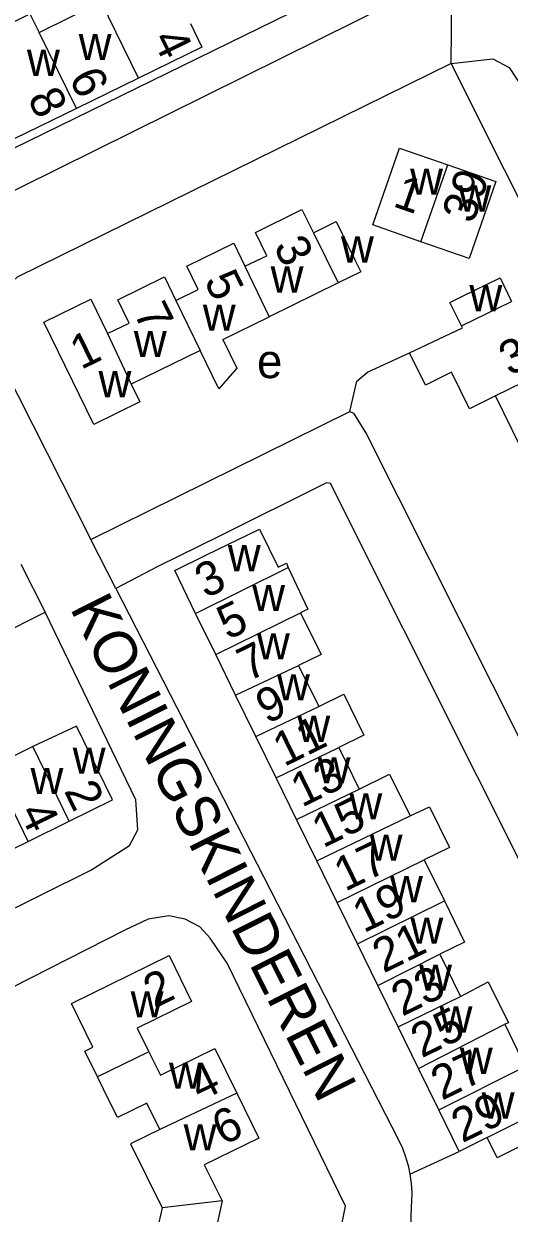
# Model space of a CAD drawing. Extents: x 159441 to 162086, y 388175 to 389787.
# Drawn here: x 161637.2 to 161694.2, y 388554.8 to 388694.6 of the extents above; entities that cross this region are included whole.
import ezdxf

# ---------------------------------------------------------------- set-up
doc = ezdxf.new("R2010")
doc.units = 0
for name, color, linetype in [('BLT_Basislijn', 7, 'Continuous'), ('BLT_Bebouwing', 7, 'Continuous'), ('BLT_Centroide', 7, 'Continuous'), ('BLT_Huisnummer', 7, 'Continuous'), ('BLT_Huisnummer_ tussenligend', 7, 'Continuous'), ('BLT_Onderverdeling_panden', 7, 'Continuous'), ('BLT_Straatnaam', 7, 'Continuous'), ('BLT_Vlakafsluiter', 7, 'Continuous')]:
    doc.layers.add(name, color=color, linetype=linetype)

msp = doc.modelspace()

# ---------------------------------------------------------------- linework, layer by layer
at = {"layer": 'BLT_Basislijn'}
for p, q in [((161647.97, 388628.23), (161645.03, 388633.99)), ((161636.83, 388631.07), (161639.68, 388625.42)), ((161596.89, 388604.02), (161639.68, 388625.42))]:
    msp.add_line(p, q, dxfattribs=at)
for points in [[(161578.12, 388651.71), (161684.78, 388703.89)], [(161685.4, 388696.77), (161683.76, 388696.15), (161680.57, 388697.06), (161588.6, 388651.51)], [(161687.38, 388689.93), (161692.29, 388690.47), (161694.21, 388689.46), (161697.24, 388684.8), (161705.87, 388667.98)], [(161687.38, 388689.93), (161636.39, 388664.83), (161633.72, 388662.46), (161632.99, 388658.94), (161633.07, 388657.62), (161645.03, 388633.99)], [(161699.94, 388664.93), (161687.38, 388689.93)], [(161675.47, 388649.04), (161676.32, 388652.58), (161677.56, 388653.64), (161682.48, 388655.92)], [(161645.03, 388633.99), (161675.47, 388649.04)], [(161675.47, 388649.04), (161675.89, 388648.83), (161677.43, 388646.38), (161718.1, 388565.45)], [(161700.24, 388567.96), (161707.73, 388571.69), (161673.2, 388640.55), (161672.73, 388640.65), (161660.17, 388634.37), (161652.91, 388630.82), (161647.97, 388628.23)], [(161647.97, 388628.23), (161681.21, 388563.42), (161681.65, 388562.44), (161682.03, 388561.43), (161682.33, 388560.4), (161682.54, 388559.38)], [(161609.65, 388577.57), (161645.06, 388595.11), (161649.6, 388598.01), (161650.55, 388599.86), (161650.33, 388603.36), (161639.68, 388625.42)], [(161663.91, 388500), (161674.95, 388555.6), (161661.05, 388584.17), (161659.08, 388587.13), (161657.86, 388588.44), (161656.13, 388589.35), (161654.21, 388589.74), (161651.76, 388589.36), (161649.03, 388588.05), (161604.73, 388565.54), (161604.29, 388565.36), (161603.88, 388565.12), (161603.52, 388564.82), (161603.22, 388564.45), (161602.98, 388564.04), (161602.82, 388563.6), (161602.73, 388563.14), (161602.72, 388562.66), (161602.8, 388562.2), (161602.94, 388561.75), (161603.06, 388561.5), (161605.95, 388555.2), (161608.55, 388550.23)], [(161682.54, 388559.38), (161688.31, 388562.06)], [(161682.54, 388559.38), (161682.69, 388558.28), (161682.76, 388557.21), (161682.74, 388556.13), (161682.7, 388555.61), (161682.37, 388545.64), (161682.35, 388544.95), (161682.4, 388544.26), (161682.54, 388543.58), (161682.76, 388542.92), (161683.04, 388542.29), (161683.4, 388541.7), (161683.83, 388541.16), (161684.31, 388540.67), (161684.85, 388540.23), (161685.44, 388539.86), (161686.06, 388539.57), (161686.71, 388539.34), (161687.39, 388539.19), (161687.69, 388539.15), (161721.9, 388532.46), (161722.81, 388532.27)]]:
    msp.add_lwpolyline(points, dxfattribs=at)
at = {"layer": 'BLT_Bebouwing'}
for p, q in [((161638.97, 388693.57), (161646.27, 388697.19)), ((161660.54, 388657.5), (161665.98, 388660.17)), ((161638.23, 388609.64), (161633.41, 388607.27)), ((161638.82, 388609.93), (161638.23, 388609.64)), ((161637.69, 388598.5), (161642.51, 388600.88)), ((161632.84, 388596.11), (161637.69, 388598.5))]:
    msp.add_line(p, q, dxfattribs=at)
for points in [[(161631.69, 388689.99), (161633.71, 388690.98), (161632.62, 388693.2), (161637.88, 388695.79), (161638.97, 388693.57)], [(161656.75, 388694.62), (161658.1, 388691.85), (161650.66, 388688.22)], [(161650.66, 388688.22), (161643.35, 388684.65)], [(161643.35, 388684.65), (161636.03, 388681.07)], [(161683.83, 388668.99), (161678.17, 388670.96), (161681.31, 388680), (161686.98, 388678.04)], [(161686.98, 388678.04), (161692.64, 388676.07), (161689.49, 388667.02), (161683.83, 388668.99)], [(161665.71, 388667.34), (161664.39, 388670.06), (161669.85, 388672.76), (161671.19, 388670.03)], [(161671.19, 388670.03), (161673.88, 388671.35), (161676.08, 388666.86), (161676.77, 388665.45), (161674.09, 388664.14)], [(161657.66, 388663.38), (161656.32, 388666.12), (161661.83, 388668.82), (161663.15, 388666.1)], [(161663.15, 388666.1), (161665.71, 388667.34)], [(161649.55, 388659.42), (161648.23, 388662.15), (161653.69, 388664.84), (161655.03, 388662.09)], [(161674.09, 388664.14), (161665.98, 388660.17)], [(161688.59, 388659.09), (161687.24, 388661.85), (161688.65, 388662.54), (161693.14, 388664.74), (161694.49, 388661.96)], [(161655.03, 388662.09), (161657.66, 388663.38)], [(161649.79, 388652.24), (161650.81, 388650.15), (161645.4, 388647.5), (161639.51, 388659.53), (161645.03, 388662.23), (161646.99, 388658.18)], [(161646.99, 388658.18), (161649.55, 388659.42)], [(161682.48, 388655.92), (161688.71, 388658.85), (161688.59, 388659.09)], [(161660.54, 388657.5), (161662.19, 388654.13), (161660.1, 388651.69), (161657.89, 388656.21)], [(161657.89, 388656.21), (161649.79, 388652.24)], [(161692.6, 388650.88), (161689.53, 388649.33), (161687.42, 388653.66), (161684.36, 388652.13), (161682.48, 388655.92)], [(161696.56, 388642.79), (161692.6, 388650.88)], [(161657.36, 388625.3), (161654.9, 388630.33), (161658.65, 388632.17), (161664.88, 388635.21), (161667.07, 388630.72), (161668.02, 388631.19), (161668.25, 388630.7)], [(161668.25, 388630.7), (161670.53, 388625.8), (161669.69, 388625.37)], [(161659.73, 388620.45), (161657.36, 388625.3)], [(161669.69, 388625.37), (161672.09, 388620.47), (161669.45, 388619.18)], [(161662.06, 388615.7), (161659.73, 388620.45)], [(161669.45, 388619.18), (161671.82, 388614.35)], [(161664.45, 388610.82), (161662.06, 388615.7)], [(161671.82, 388614.35), (161674.78, 388615.8), (161677.13, 388610.99), (161674.17, 388609.54)], [(161642.51, 388600.88), (161647.58, 388603.38), (161643.37, 388612.02), (161638.82, 388609.93)], [(161666.83, 388605.95), (161664.45, 388610.82)], [(161674.17, 388609.54), (161676.58, 388604.62)], [(161669.22, 388601.07), (161666.83, 388605.95)], [(161676.58, 388604.62), (161680.15, 388606.38), (161682.55, 388601.49)], [(161682.55, 388601.49), (161684.85, 388602.56), (161687.18, 388597.79), (161684.21, 388596.34)], [(161671.61, 388596.2), (161669.22, 388601.07)], [(161673.99, 388591.32), (161671.61, 388596.2)], [(161684.21, 388596.34), (161686.59, 388591.49)], [(161676.38, 388586.44), (161673.99, 388591.32)], [(161686.59, 388591.49), (161688.96, 388586.65), (161686.06, 388585.23)], [(161678.77, 388581.57), (161676.38, 388586.44)], [(161642.75, 388579.44), (161654.25, 388585.1), (161656.89, 388579.69), (161650.49, 388576.55), (161651.85, 388573.77)], [(161686.06, 388585.23), (161688.48, 388580.28)], [(161681.15, 388576.69), (161678.77, 388581.57)], [(161688.48, 388580.28), (161691.74, 388582), (161694.12, 388577.15), (161693.68, 388576.99)], [(161645.28, 388574.31), (161642.75, 388579.44)], [(161683.54, 388571.81), (161681.15, 388576.69)], [(161693.68, 388576.99), (161696.1, 388572.05)], [(161645.83, 388570.81), (161644.33, 388573.85), (161645.28, 388574.31)], [(161651.85, 388573.77), (161653.22, 388571), (161659.62, 388574.14), (161662.2, 388568.88)], [(161685.92, 388566.94), (161683.54, 388571.81)], [(161653.14, 388564.64), (161651.61, 388567.74), (161648.18, 388566.04), (161646.54, 388569.36), (161645.83, 388570.81)], [(161662.2, 388568.88), (161664.78, 388563.61), (161658.37, 388560.47), (161660.46, 388556.25)], [(161688.31, 388562.06), (161685.92, 388566.94)], [(161653.14, 388564.64), (161649.7, 388562.95), (161653.41, 388555.43)], [(161695.63, 388565.67), (161696.8, 388563.28), (161692.79, 388561.31), (161691.63, 388563.68)], [(161691.63, 388563.68), (161688.31, 388562.06)], [(161660.46, 388556.25), (161659.48, 388551.74), (161666.45, 388550.26), (161665.22, 388544.53)], [(161653.41, 388555.43), (161652.85, 388552.82), (161656.62, 388552.02), (161655.46, 388546.55)]]:
    msp.add_lwpolyline(points, dxfattribs=at)
at = {"layer": 'BLT_Onderverdeling_panden'}
for p, q in [((161650.66, 388688.22), (161646.27, 388697.19)), ((161643.35, 388684.65), (161638.97, 388693.57)), ((161683.83, 388668.99), (161686.98, 388678.04)), ((161671.19, 388670.03), (161674.09, 388664.14)), ((161663.15, 388666.1), (161665.98, 388660.17)), ((161655.03, 388662.09), (161657.89, 388656.21)), ((161688.59, 388659.09), (161694.49, 388661.96)), ((161646.99, 388658.18), (161649.79, 388652.24)), ((161701.2, 388655.1), (161692.6, 388650.88)), ((161657.36, 388625.3), (161668.25, 388630.7)), ((161659.73, 388620.45), (161669.69, 388625.37)), ((161662.06, 388615.7), (161669.45, 388619.18)), ((161664.45, 388610.82), (161671.82, 388614.35)), ((161642.51, 388600.88), (161638.23, 388609.64)), ((161666.83, 388605.95), (161674.17, 388609.54)), ((161637.69, 388598.5), (161633.41, 388607.27)), ((161669.22, 388601.07), (161676.58, 388604.62)), ((161671.61, 388596.2), (161682.55, 388601.49)), ((161673.99, 388591.32), (161684.21, 388596.34)), ((161676.38, 388586.44), (161686.59, 388591.49)), ((161678.77, 388581.57), (161686.06, 388585.23)), ((161681.15, 388576.69), (161688.48, 388580.28)), ((161683.54, 388571.81), (161693.68, 388576.99)), ((161651.85, 388573.77), (161645.83, 388570.81)), ((161685.92, 388566.94), (161696.1, 388572.05)), ((161662.2, 388568.88), (161653.14, 388564.64)), ((161691.63, 388563.68), (161695.63, 388565.67)), ((161660.46, 388556.25), (161653.41, 388555.43))]:
    msp.add_line(p, q, dxfattribs=at)
at = {"layer": 'BLT_Vlakafsluiter'}
msp.add_line((161687.38, 388689.93), (161687.48, 388698.35), dxfattribs=at)

# ---------------------------------------------------------------- texts
at = {"layer": 'BLT_Centroide'}
for s, p in [('w', (161643.61, 388690.34)), ('w', (161637.53, 388688.48)), ('w', (161682.56, 388674.5)), ('w', (161688.23, 388672.53)), ('w', (161674.44, 388666.54)), ('w', (161666.17, 388663.01)), ('w', (161689.53, 388660.82)), ('w', (161658.2, 388658.53)), ('w', (161650.09, 388655.42)), ('e', (161664.57, 388652.95)), ('w', (161645.94, 388650.71)), ('w', (161661.14, 388630.25)), ('w', (161664, 388625.56)), ('w', (161664.56, 388619.88)), ('w', (161666.92, 388615.06)), ('w', (161669.31, 388610.19)), ('w', (161642.91, 388606.44)), ('w', (161671.69, 388605.31)), ('w', (161637.95, 388604.06)), ('w', (161675.43, 388601.09)), ('w', (161677.81, 388596.22)), ('w', (161680.2, 388591.34)), ('w', (161682.59, 388586.47)), ('w', (161683.62, 388580.94)), ('w', (161649.72, 388577.8)), ('w', (161686.02, 388576.03)), ('w', (161688.4, 388571.16)), ('w', (161654.23, 388569.41)), ('w', (161690.97, 388565.91)), ('w', (161655.95, 388562.16))]:
    msp.add_text(s, height=4, dxfattribs=at).set_placement(p)
at = {"layer": 'BLT_Huisnummer'}
for s, rotation, p in [('4', 296.0386, (161652.22, 388692.83)), ('6', 296.0386, (161642.41, 388688.25)), ('1', 340.8186, (161680.41, 388673.19)), ('39', 70.8239, (161689.97, 388670.98)), ('3', 296.0935, (161666.46, 388668.45)), ('7', 296.0935, (161650.02, 388660.65)), ('1', 26.0937, (161643.89, 388653.89)), ('37', 26.0328, (161694.27, 388653.14)), ('3', 26.0729, (161658.55, 388627.01)), ('7', 26.0729, (161663.53, 388617.23)), ('11', 26.0729, (161667.74, 388607.22)), ('2', 296.0358, (161641.84, 388604.44)), ('15', 26.0729, (161672.32, 388597.66)), ('19', 26.0729, (161677.1, 388587.67)), ('2', 26.1589, (161652.5, 388578.8)), ('23', 26.0729, (161681.63, 388577.87)), ('29', 26.0729, (161688.69, 388563)), ('6', 26.1589, (161660.58, 388562.7))]:
    msp.add_text(s, height=4, rotation=rotation, dxfattribs=at).set_placement(p)
at = {"layer": 'BLT_Huisnummer_ tussenligend'}
for s, rotation, p in [('8', 296.0386, (161637.55, 388685.88)), ('5', 296.0935, (161658.29, 388664.41)), ('5', 26.0729, (161661.15, 388622.12)), ('9', 26.0729, (161665.72, 388612.24)), ('13', 26.0729, (161669.83, 388602.44)), ('4', 296.0358, (161636.56, 388601.93)), ('17', 26.0729, (161674.91, 388592.55)), ('21', 26.0729, (161679.43, 388582.96)), ('25', 26.0729, (161683.92, 388572.98)), ('27', 26.0729, (161686.29, 388567.99)), ('4', 26.1589, (161657.88, 388567.89))]:
    msp.add_text(s, height=4, rotation=rotation, dxfattribs=at).set_placement(p)
at = {"layer": 'BLT_Straatnaam'}
msp.add_text('KONINGSKINDEREN', height=5, rotation=296.7504, dxfattribs=at).set_placement((161642.53, 388625.93))

doc.saveas('drawing.dxf')
